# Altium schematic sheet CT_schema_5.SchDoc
size 445 x 328 mm
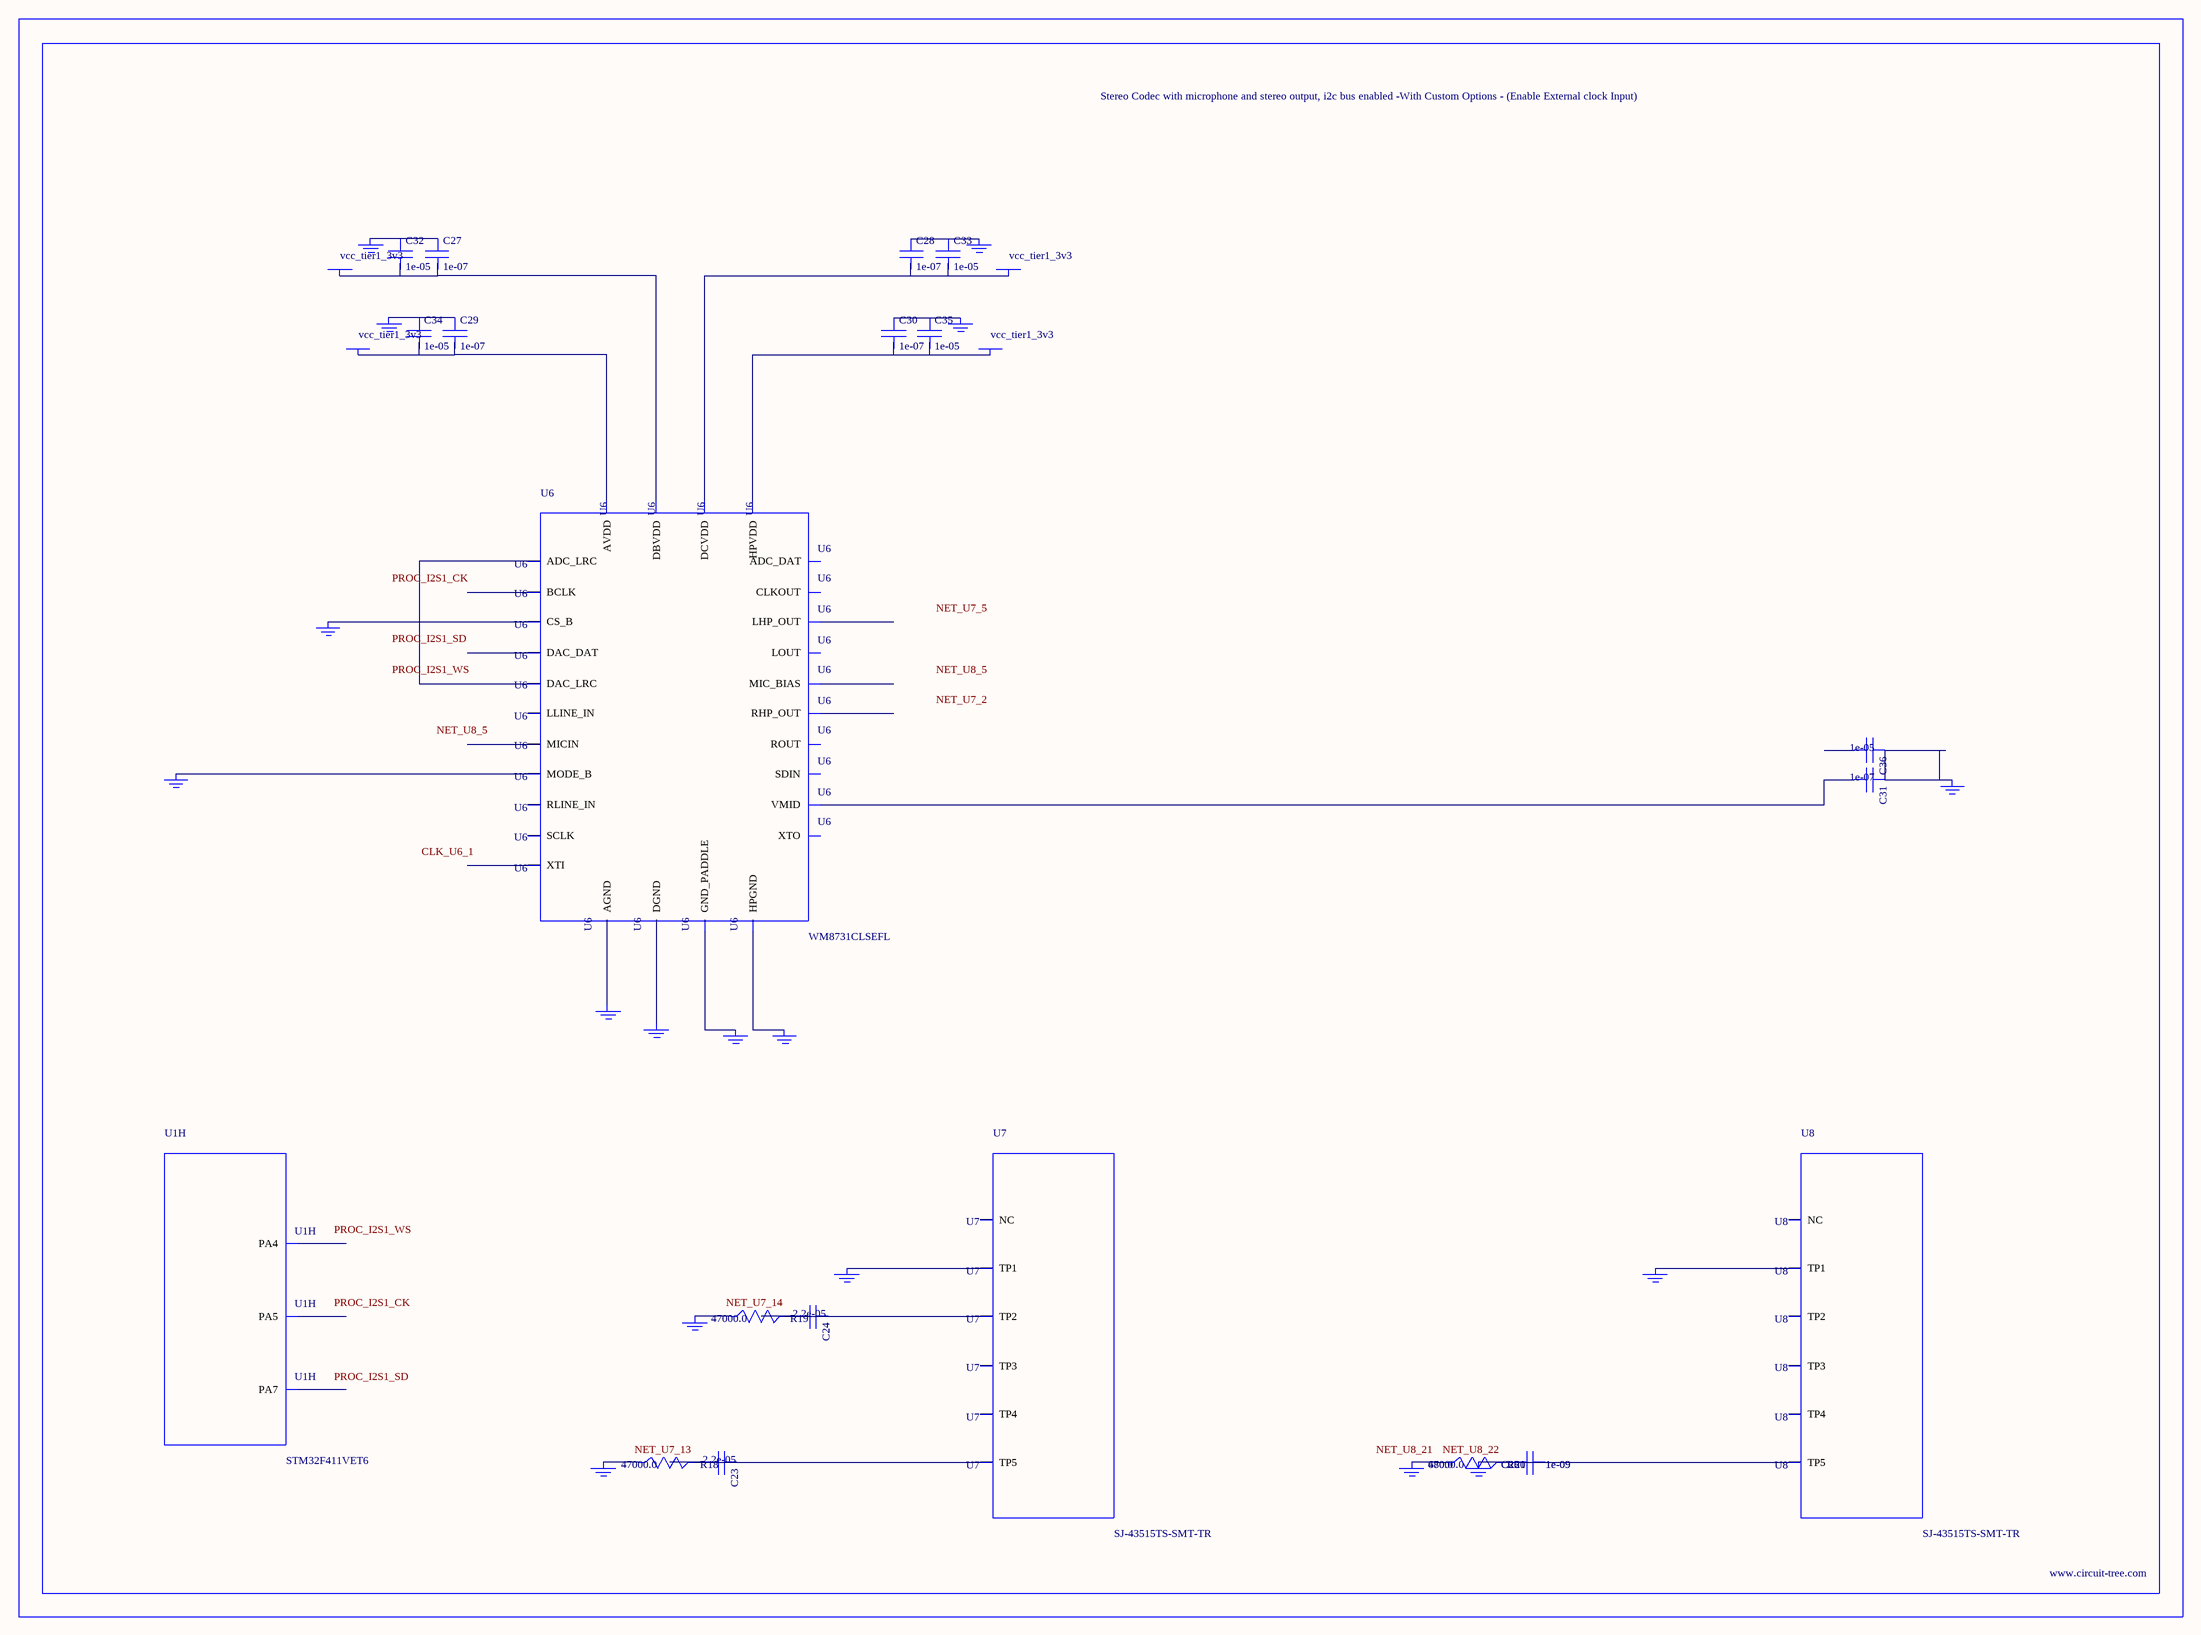
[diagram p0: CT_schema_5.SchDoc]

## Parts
BORDER4  (no value)
C23  2.2e-05  [C1210]
C24  2.2e-05  [C1210]
C25  1e-09  [C0402]
C26  1e-09  [C0402]
C27  1e-07  [C0402]
C28  1e-07  [C0402]
C29  1e-07  [C0402]
C30  1e-07  [C0402]
C31  1e-07  [C0402]
C32  1e-05  [C0805]
C33  1e-05  [C0805]
C34  1e-05  [C0805]
C35  1e-05  [C0805]
C36  1e-05  [C0805]
GND_INSTANCE_4_0  (no value)
GND_INSTANCE_4_1  (no value)
GND_INSTANCE_4_2  (no value)
GND_INSTANCE_4_3  (no value)
GND_INSTANCE_4_4  (no value)
GND_INSTANCE_4_5  (no value)
GND_INSTANCE_4_6  (no value)
GND_INSTANCE_4_7  (no value)
GND_INSTANCE_4_8  (no value)
GND_INSTANCE_4_9  (no value)
GND_INSTANCE_4_10  (no value)
GND_INSTANCE_4_11  (no value)
GND_INSTANCE_4_12  (no value)
GND_INSTANCE_4_13  (no value)
GND_INSTANCE_4_14  (no value)
GND_INSTANCE_4_15  (no value)
GND_INSTANCE_4_16  (no value)
POWER_INSTANCE_4_0  vcc_tier1_3v3
POWER_INSTANCE_4_1  vcc_tier1_3v3
POWER_INSTANCE_4_2  vcc_tier1_3v3
POWER_INSTANCE_4_3  vcc_tier1_3v3
R18  47000.0  [R0603]
R19  47000.0  [R0603]
R20  47000.0  [R0603]
R21  680.0  [R0603]
U1  STM32F411VET6  [LQFP100]  (part H of 10)
U6  WM8731CLSEFL  [QFN-28]
U7  SJ-43515TS-SMT-TR  [SJ-43515TS-SMT-TR]
U8  SJ-43515TS-SMT-TR  [SJ-43515TS-SMT-TR]

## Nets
NetC23_1: C23.1 C23.2 R18.2 U7.5(TP5)
NetC24_1: C24.1 C24.2 R19.2 U7.2(TP2)
NetC25_1: C25.1 C25.2 C26.1 C26.2 GND_INSTANCE_4_16.0(GND) R20.2 R21.2 U8.5(TP5)
NetC27_1: C27.1 C32.1 GND_INSTANCE_4_1.0(GND)
NetC27_2: C27.2 C32.2 POWER_INSTANCE_4_1.0(PWR) U6.5(DBVDD)
NetC28_1: C28.1 C33.1 GND_INSTANCE_4_0.0(GND)
NetC28_2: C28.2 C33.2 POWER_INSTANCE_4_0.0(PWR) U6.3(DCVDD)
NetC29_1: C29.1 C34.1 GND_INSTANCE_4_4.0(GND)
NetC29_2: C29.2 C34.2 POWER_INSTANCE_4_3.0(PWR) U6.18(AVDD)
NetC30_1: C30.1 C35.1 GND_INSTANCE_4_2.0(GND)
NetC30_2: C30.2 C35.2 POWER_INSTANCE_4_2.0(PWR) U6.12(HPVDD)
NetC31_1: C31.1 C36.1 GND_INSTANCE_4_5.0(GND)
NetC31_2: C31.2 U6.20(VMID)
NetGND_INSTANCE_4_3_0: GND_INSTANCE_4_3.0(GND) U6.15(HPGND)
NetGND_INSTANCE_4_6_0: GND_INSTANCE_4_6.0(GND) U6.25(MODE_B)
NetGND_INSTANCE_4_7_0: GND_INSTANCE_4_7.0(GND) U6.26(CS_B)
NetGND_INSTANCE_4_8_0: GND_INSTANCE_4_8.0(GND) U6.29(GND_PADDLE)
NetGND_INSTANCE_4_9_0: GND_INSTANCE_4_9.0(GND) U6.4(DGND)
NetGND_INSTANCE_4_10_0: GND_INSTANCE_4_10.0(GND) U6.19(AGND)
NetGND_INSTANCE_4_11_0: GND_INSTANCE_4_11.0(GND) U7.1(TP1)
NetGND_INSTANCE_4_12_0: GND_INSTANCE_4_12.0(GND) R19.1
NetGND_INSTANCE_4_13_0: GND_INSTANCE_4_13.0(GND) R18.1
NetGND_INSTANCE_4_14_0: GND_INSTANCE_4_14.0(GND) U8.1(TP1)
NetGND_INSTANCE_4_15_0: GND_INSTANCE_4_15.0(GND) R20.1 R21.1
NetU6_9: U6.9(DAC_LRC) U6.11(ADC_LRC)

Not connected (* = marked no-connect by the designer): C36 2; U1 29(PA4) 30(PA5) 32(PA7); U6 1(XTI) 2(XTO) 6(CLKOUT) 7(BCLK) 8(DAC_DAT) 10(ADC_DAT) 13(LHP_OUT) 14(RHP_OUT) 16(LOUT) 17(ROUT) 21(MIC_BIAS) 22(MICIN) 23(RLINE_IN) 24(LLINE_IN) 27(SDIN) 28(SCLK); U7 3(TP3) 4(TP4) 6(NC); U8 2(TP2) 3(TP3) 4(TP4) 6(NC)

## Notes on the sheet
- Labels drawn without touching a wire or pin: CLK_U6_1, NET_U7_2, NET_U7_5, NET_U7_13, NET_U7_14, NET_U8_5, NET_U8_21, NET_U8_22, PROC_I2S1_CK, PROC_I2S1_SD, PROC_I2S1_WS

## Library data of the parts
BORDER4 = BORDER_PAGE4
C23 C24 = C1210C224K5RACTU
C25 C26 = C0402C102K3RAC
C27-C31 = C0402C104K3RACTU
C32-C36 = C0805C106K8RACTU
GND_INSTANCE_4_0-GND_INSTANCE_4_16 = GND
POWER_INSTANCE_4_0-POWER_INSTANCE_4_3 = PWR
R18-R20 = RC0603JR-0747KL
R21 = RC0603JR-07680RL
